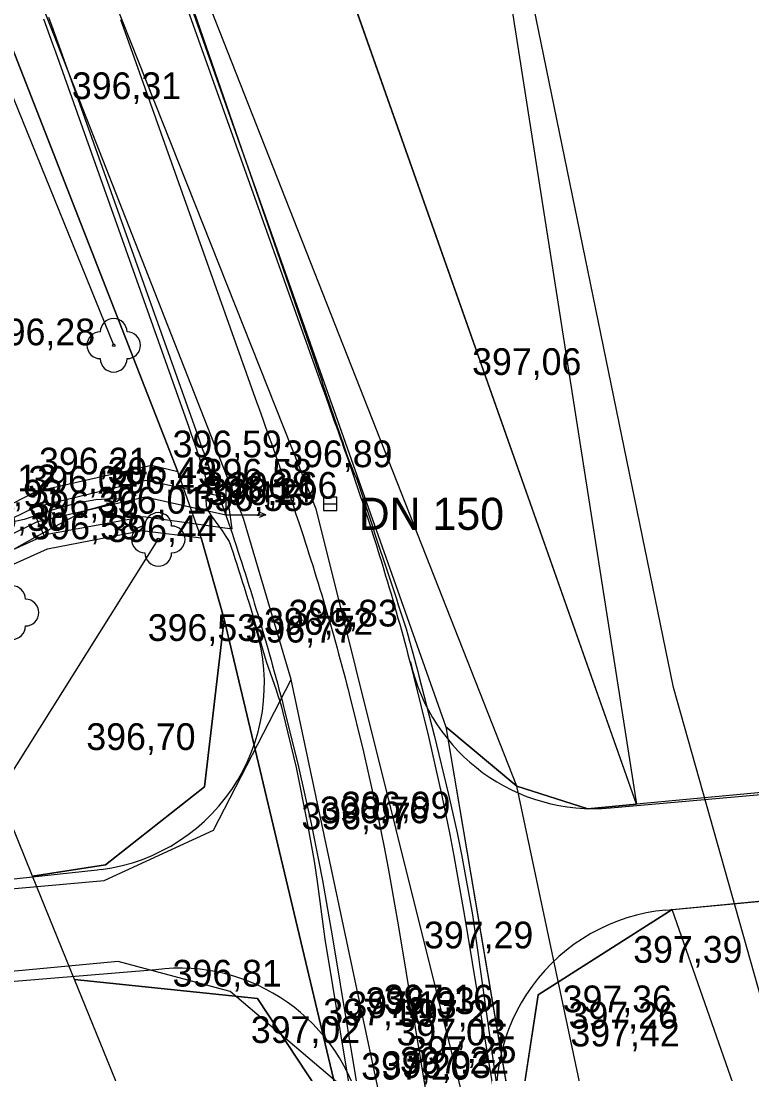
# Model space of a CAD drawing. Extents: x -574342 to -507939, y -1144044 to -1123894.
# Drawn here: x -508438.6 to -508411.24, y -1143262.87 to -1143223.48 of the extents above; entities that cross this region are included whole.
import ezdxf

# ---------------------------------------------------------------- set-up
doc = ezdxf.new("R2010")
doc.units = 0
for name, color, linetype in [('01_PARCELY_NAVRH_PC', 7, 'Continuous'), ('01_PARCELY_NAVRH_VHO', 7, 'Continuous'), ('01_PARCELY_NAVRH_ZPF', 7, 'Continuous'), ('01_PARCELY_NAVRH_ŽP', 7, 'Continuous'), ('1000', 7, 'Continuous'), ('15', 7, 'Continuous'), ('21', 7, 'Continuous'), ('37', 7, 'Continuous'), ('42', 7, 'Continuous'), ('52', 7, 'Continuous'), ('54', 7, 'Continuous'), ('55', 7, 'Continuous'), ('60', 7, 'Continuous'), ('61', 7, 'Continuous'), ('cesty', 7, 'Continuous'), ('Level 255', 7, 'Continuous'), ('VRST VEDL', 7, 'Continuous')]:
    doc.layers.add(name, color=color, linetype=linetype)

msp = doc.modelspace()

# ---------------------------------------------------------------- linework, layer by layer
at = {"layer": '01_PARCELY_NAVRH_PC'}
for points in [[(-508426.41, -1143265.09), (-508431, -1143245.85), (-508431.86, -1143242.81), (-508432.73, -1143240.34), (-508445.99, -1143206.42), (-508454.33, -1143183.49), (-508456.87, -1143173.84), (-508463.3, -1143163.03), (-508476.26, -1143134.7), (-508479.46, -1143126.74), (-508474.05, -1143124.14), (-508467.92, -1143139.18), (-508459.97, -1143152.33), (-508456.09, -1143158.71), (-508451.57, -1143168.14), (-508437.66, -1143207.58), (-508425.52, -1143241.92), (-508422.7, -1143249.88), (-508420.08, -1143265.35)], [(-508026.763, -1143130.616), (-508028.05, -1143130.95), (-508188.91, -1143212.74), (-508197.69, -1143215.86), (-508325.49, -1143244.3), (-508415.56, -1143252.78), (-508417.38, -1143252.95), (-508420.04, -1143252.1), (-508422.7, -1143249.88), (-508420.08, -1143265.35), (-508419.24, -1143259.91), (-508414.23, -1143256.72), (-508401.25, -1143255.47), (-508381.42, -1143253.61), (-508325.37, -1143248.48), (-508191.76, -1143218.68), (-508026.763, -1143135.132)]]:
    msp.add_lwpolyline(points, dxfattribs=at)
msp.add_lwpolyline([(-508431, -1143245.85), (-508426.41, -1143265.09), (-508429.75, -1143260.04), (-508436.6, -1143259.34), (-508438.17, -1143255.47), (-508435.43, -1143255.05), (-508431.73, -1143252.13)], close=True, dxfattribs=at)
at = {"layer": '01_PARCELY_NAVRH_VHO'}
msp.add_lwpolyline([(-508433.97, -1143265.8), (-508436.6, -1143259.34), (-508438.17, -1143255.47), (-508441.16, -1143248.09), (-508442.91, -1143245.61), (-508437.61, -1143243.22), (-508434.06, -1143242.54), (-508431.86, -1143242.81), (-508432.73, -1143240.34), (-508433.72, -1143240.11), (-508438.05, -1143241.09), (-508444.11, -1143244.2), (-508446.56, -1143243.12), (-508452.58, -1143244.39), (-508461.81, -1143244.49), (-508467.98, -1143243.62)], dxfattribs=at)
at = {"layer": '01_PARCELY_NAVRH_ZPF'}
msp.add_lwpolyline([(-508263.293, -1143480.706), (-508286.971, -1143456.793), (-508322.95, -1143422.01), (-508338.96, -1143386.69), (-508345.08, -1143368.8), (-508351.18, -1143342.58), (-508355.53, -1143335.68), (-508361.58, -1143328.14), (-508368.91, -1143322.84), (-508376.72, -1143318.72), (-508388.31, -1143315.9), (-508393.87, -1143311.09), (-508396.73, -1143306.67), (-508414.23, -1143256.72), (-508401.25, -1143255.47), (-508393.61, -1143260.11), (-508380.74, -1143302.76), (-508356.16, -1143314.16), (-508344.92, -1143326.36), (-508313.43, -1143410.52), (-508253.01, -1143468.5)], dxfattribs=at)
at = {"layer": '01_PARCELY_NAVRH_ŽP'}
for points in [[(-508540.355, -1142847.7), (-508503.94, -1143018.7), (-508499.26, -1143041.98), (-508491.15, -1143065.29), (-508474.05, -1143124.14), (-508467.92, -1143139.18), (-508459.97, -1143152.33), (-508456.09, -1143158.71), (-508451.57, -1143168.14), (-508437.66, -1143207.58), (-508425.52, -1143241.92), (-508422.7, -1143249.88), (-508420.04, -1143252.1), (-508417.38, -1143252.95), (-508415.56, -1143252.78), (-508448.24, -1143160.16), (-508453.75, -1143145.01), (-508465.11, -1143123.03), (-508471.48, -1143106.99), (-508484.55, -1143061.98), (-508495.62, -1143031.06), (-508523.23, -1142904.28), (-508534.61, -1142847.7)], [(-508338.96, -1143386.69), (-508345.08, -1143368.8), (-508351.18, -1143342.58), (-508355.53, -1143335.68), (-508361.58, -1143328.14), (-508368.91, -1143322.84), (-508376.72, -1143318.72), (-508388.31, -1143315.9), (-508393.87, -1143311.09), (-508396.73, -1143306.67), (-508414.23, -1143256.72), (-508419.24, -1143259.91), (-508420.08, -1143265.35), (-508416.18, -1143288.91), (-508414.34, -1143296.2), (-508410.3, -1143304.94), (-508406.96, -1143310.33), (-508402.64, -1143313.55), (-508394.5, -1143317.14), (-508377.05, -1143323.29), (-508363.05, -1143330.55), (-508352.96, -1143343.32), (-508344.87, -1143376.79)]]:
    msp.add_lwpolyline(points, dxfattribs=at)
for points in [[(-508415.56, -1143252.78), (-508448.24, -1143160.16), (-508453.75, -1143145.01), (-508465.11, -1143123.03), (-508471.48, -1143106.99), (-508484.55, -1143061.98), (-508446.15, -1143057.71)], [(-508455.43, -1143236.54), (-508453.14, -1143234.1), (-508452.04, -1143229.57), (-508450.69, -1143221.56), (-508452.8, -1143209.75), (-508452.72, -1143198.2), (-508454.33, -1143183.49), (-508445.99, -1143206.42), (-508432.73, -1143240.34), (-508433.72, -1143240.11), (-508438.05, -1143241.09), (-508444.11, -1143244.2), (-508446.56, -1143243.12), (-508452.58, -1143244.39)], [(-508442.91, -1143245.61), (-508437.61, -1143243.22), (-508434.06, -1143242.54), (-508431.86, -1143242.81), (-508431, -1143245.85), (-508431.73, -1143252.13), (-508435.43, -1143255.05), (-508438.17, -1143255.47), (-508441.16, -1143248.09)], [(-508436.6, -1143259.34), (-508429.75, -1143260.04), (-508426.41, -1143265.09), (-508422.28, -1143289.33), (-508418.17, -1143303.49), (-508414.82, -1143312.69), (-508407.39, -1143320.93), (-508402.47, -1143323.55), (-508412.73, -1143323), (-508414.59, -1143317.71), (-508420.1, -1143305.91), (-508426.78, -1143287.77), (-508433.97, -1143265.8)]]:
    msp.add_lwpolyline(points, close=True, dxfattribs=at)
at = {"layer": '1000'}
for points in [[(-508432.412, -1143222.893), (-508427.412, -1143236.927), (-508427.335, -1143237.143), (-508427.258, -1143237.36), (-508427.181, -1143237.576), (-508427.104, -1143237.793), (-508427.027, -1143238.009), (-508426.95, -1143238.226), (-508426.873, -1143238.442), (-508426.796, -1143238.659), (-508426.719, -1143238.875), (-508426.641, -1143239.091), (-508426.572, -1143239.287), (-508426.564, -1143239.308), (-508426.485, -1143239.53), (-508426.407, -1143239.752), (-508426.329, -1143239.975), (-508426.252, -1143240.197), (-508426.176, -1143240.42), (-508426.099, -1143240.643), (-508426.024, -1143240.866), (-508425.949, -1143241.089), (-508425.874, -1143241.312), (-508425.829, -1143241.447), (-508425.8, -1143241.536), (-508425.726, -1143241.76), (-508425.653, -1143241.983), (-508425.581, -1143242.207), (-508425.509, -1143242.432), (-508425.437, -1143242.656), (-508425.366, -1143242.881), (-508425.295, -1143243.105), (-508425.225, -1143243.33), (-508425.156, -1143243.555), (-508425.135, -1143243.624), (-508425.087, -1143243.78), (-508425.019, -1143244.006), (-508424.951, -1143244.231), (-508424.883, -1143244.457), (-508424.816, -1143244.683), (-508424.75, -1143244.909), (-508424.684, -1143245.135), (-508424.619, -1143245.361), (-508424.554, -1143245.587), (-508424.49, -1143245.814), (-508424.489, -1143245.816), (-508424.426, -1143246.041), (-508424.363, -1143246.267), (-508424.3, -1143246.494), (-508424.238, -1143246.722), (-508424.176, -1143246.949), (-508424.115, -1143247.176), (-508424.054, -1143247.404), (-508423.994, -1143247.631), (-508423.934, -1143247.859), (-508423.892, -1143248.022), (-508423.345, -1143250.24), (-508422.847, -1143252.47), (-508422.554, -1143253.907), (-508422.399, -1143254.711), (-508422.001, -1143256.961), (-508420.867, -1143263.821)], [(-508432.226, -1143222.827), (-508427.357, -1143236.907), (-508427.284, -1143237.125), (-508427.209, -1143237.343), (-508427.135, -1143237.56), (-508427.061, -1143237.777), (-508426.987, -1143237.995), (-508426.912, -1143238.212), (-508426.838, -1143238.43), (-508426.763, -1143238.647), (-508426.688, -1143238.864), (-508426.613, -1143239.081), (-508426.546, -1143239.277), (-508426.538, -1143239.299), (-508426.462, -1143239.522), (-508426.386, -1143239.745), (-508426.31, -1143239.968), (-508426.216, -1143240.185), (-508426.124, -1143240.402), (-508426.031, -1143240.619), (-508425.953, -1143240.842), (-508425.875, -1143241.064), (-508425.799, -1143241.287), (-508425.755, -1143241.423), (-508425.725, -1143241.511), (-508425.652, -1143241.735), (-508425.579, -1143241.959), (-508425.506, -1143242.183), (-508425.434, -1143242.408), (-508425.362, -1143242.632), (-508425.29, -1143242.857), (-508425.219, -1143243.081), (-508425.146, -1143243.306), (-508425.071, -1143243.529), (-508425.048, -1143243.598), (-508424.996, -1143243.752), (-508424.921, -1143243.976), (-508424.846, -1143244.2), (-508424.772, -1143244.424), (-508424.698, -1143244.648), (-508424.624, -1143244.872), (-508424.55, -1143245.096), (-508424.477, -1143245.32), (-508424.405, -1143245.545), (-508424.332, -1143245.769), (-508424.331, -1143245.772), (-508424.26, -1143245.994), (-508424.188, -1143246.219), (-508424.123, -1143246.446), (-508424.061, -1143246.673), (-508423.998, -1143246.901), (-508423.936, -1143247.128), (-508423.874, -1143247.356), (-508423.813, -1143247.584), (-508423.752, -1143247.812), (-508423.708, -1143247.974), (-508423.137, -1143250.192), (-508422.599, -1143252.418), (-508422.277, -1143253.853), (-508422.116, -1143254.658), (-508421.696, -1143256.911), (-508420.73, -1143263.798)], [(-508437.754, -1143223.398), (-508437.642, -1143223.707), (-508437.531, -1143224.017), (-508437.419, -1143224.327), (-508437.307, -1143224.637), (-508432.319, -1143238.675), (-508432.242, -1143238.892), (-508432.165, -1143239.108), (-508432.089, -1143239.325), (-508432.016, -1143239.543), (-508431.946, -1143239.762), (-508431.876, -1143239.981), (-508431.807, -1143240.2), (-508431.737, -1143240.419), (-508431.668, -1143240.638), (-508431.599, -1143240.857), (-508431.625, -1143241.087), (-508431.629, -1143241.111), (-508431.677, -1143241.365), (-508431.668, -1143241.598), (-508431.591, -1143241.807), (-508431.466, -1143241.999), (-508431.331, -1143242.189), (-508431.197, -1143242.379), (-508431.062, -1143242.569), (-508430.929, -1143242.759), (-508430.802, -1143242.953), (-508430.759, -1143243.081), (-508430.732, -1143243.165), (-508430.663, -1143243.378), (-508430.593, -1143243.59), (-508430.524, -1143243.803), (-508430.455, -1143244.015), (-508430.386, -1143244.228), (-508430.318, -1143244.441), (-508430.25, -1143244.654), (-508430.184, -1143244.867), (-508430.117, -1143245.081), (-508430.097, -1143245.147), (-508430.052, -1143245.295), (-508429.986, -1143245.508), (-508429.922, -1143245.723), (-508429.858, -1143245.937), (-508429.794, -1143246.151), (-508429.732, -1143246.366), (-508429.669, -1143246.58), (-508429.608, -1143246.795), (-508429.547, -1143247.01), (-508429.486, -1143247.226), (-508429.485, -1143247.228), (-508429.42, -1143247.439), (-508429.345, -1143247.651), (-508429.272, -1143247.862), (-508429.199, -1143248.074), (-508429.126, -1143248.286), (-508429.054, -1143248.499), (-508428.983, -1143248.711), (-508428.912, -1143248.924), (-508428.847, -1143249.138), (-508428.808, -1143249.293), (-508428.301, -1143251.405), (-508427.873, -1143253.534), (-508427.631, -1143254.906), (-508427.514, -1143255.675), (-508427.224, -1143257.825), (-508426.094, -1143264.685)], [(-508437.564, -1143223.33), (-508437.454, -1143223.64), (-508437.343, -1143223.951), (-508437.233, -1143224.261), (-508437.122, -1143224.571), (-508432.123, -1143238.605), (-508432.045, -1143238.821), (-508431.968, -1143239.038), (-508431.891, -1143239.254), (-508431.814, -1143239.471), (-508431.737, -1143239.687), (-508431.66, -1143239.904), (-508431.583, -1143240.12), (-508431.506, -1143240.336), (-508431.429, -1143240.553), (-508431.351, -1143240.769), (-508431.282, -1143240.965), (-508431.275, -1143240.985), (-508431.2, -1143241.196), (-508431.125, -1143241.408), (-508431.051, -1143241.619), (-508430.978, -1143241.831), (-508430.905, -1143242.043), (-508430.833, -1143242.255), (-508430.761, -1143242.467), (-508430.689, -1143242.679), (-508430.618, -1143242.891), (-508430.575, -1143243.02), (-508430.548, -1143243.104), (-508430.478, -1143243.317), (-508430.408, -1143243.53), (-508430.339, -1143243.743), (-508430.27, -1143243.956), (-508430.202, -1143244.17), (-508430.135, -1143244.383), (-508430.068, -1143244.597), (-508430.001, -1143244.811), (-508429.935, -1143245.025), (-508429.915, -1143245.091), (-508429.869, -1143245.239), (-508429.804, -1143245.453), (-508429.74, -1143245.668), (-508429.676, -1143245.883), (-508429.612, -1143246.097), (-508429.549, -1143246.312), (-508429.486, -1143246.527), (-508429.424, -1143246.743), (-508429.362, -1143246.958), (-508429.301, -1143247.173), (-508429.301, -1143247.176), (-508429.241, -1143247.389), (-508429.18, -1143247.605), (-508429.121, -1143247.821), (-508429.062, -1143248.037), (-508429.003, -1143248.253), (-508428.945, -1143248.469), (-508428.887, -1143248.686), (-508428.83, -1143248.902), (-508428.773, -1143249.119), (-508428.733, -1143249.274), (-508428.212, -1143251.384), (-508427.739, -1143253.505), (-508427.46, -1143254.872), (-508427.313, -1143255.637), (-508426.934, -1143257.777), (-508425.8, -1143264.636)]]:
    msp.add_lwpolyline(points, dxfattribs=at)
at = {"layer": '21'}
msp.add_lwpolyline([(-508434.878, -1143223.422), (-508434.767, -1143223.732), (-508429.767, -1143237.766), (-508429.69, -1143237.982), (-508429.613, -1143238.199), (-508429.536, -1143238.415), (-508429.459, -1143238.632), (-508429.382, -1143238.848), (-508429.305, -1143239.065), (-508429.228, -1143239.281), (-508429.151, -1143239.497), (-508429.074, -1143239.714), (-508428.996, -1143239.93), (-508428.927, -1143240.126), (-508428.919, -1143240.147), (-508428.843, -1143240.363), (-508428.766, -1143240.58), (-508428.69, -1143240.797), (-508428.615, -1143241.014), (-508428.54, -1143241.231), (-508428.466, -1143241.449), (-508428.392, -1143241.666), (-508428.319, -1143241.884), (-508428.246, -1143242.102), (-508428.202, -1143242.234), (-508428.174, -1143242.32), (-508428.102, -1143242.538), (-508428.031, -1143242.757), (-508427.96, -1143242.975), (-508427.889, -1143243.194), (-508427.82, -1143243.413), (-508427.75, -1143243.632), (-508427.682, -1143243.851), (-508427.613, -1143244.07), (-508427.546, -1143244.29), (-508427.525, -1143244.358), (-508427.478, -1143244.51), (-508427.411, -1143244.73), (-508427.345, -1143244.949), (-508427.279, -1143245.17), (-508427.214, -1143245.39), (-508427.149, -1143245.61), (-508427.085, -1143245.831), (-508427.021, -1143246.052), (-508426.958, -1143246.273), (-508426.895, -1143246.494), (-508426.895, -1143246.496), (-508426.833, -1143246.715), (-508426.771, -1143246.936), (-508426.71, -1143247.158), (-508426.65, -1143247.379), (-508426.589, -1143247.601), (-508426.53, -1143247.823), (-508426.471, -1143248.045), (-508426.412, -1143248.267), (-508426.354, -1143248.489), (-508426.313, -1143248.648), (-508425.779, -1143250.812), (-508425.293, -1143252.988), (-508425.007, -1143254.39), (-508424.856, -1143255.174), (-508424.468, -1143257.369), (-508423.333, -1143264.228)], dxfattribs=at)
at = {"layer": '37'}
for points in [[(-508473.82, -1143129.8), (-508468.34, -1143141.31), (-508458.53, -1143158.76), (-508453.13, -1143170.86), (-508439.96, -1143210.5), (-508427.56, -1143241.73), (-508421.57, -1143265.72), (-508416.35, -1143292.6), (-508412.42, -1143304.7), (-508408.82, -1143311.83)], [(-508473.82, -1143129.8), (-508468.34, -1143141.31), (-508458.53, -1143158.76), (-508453.13, -1143170.86), (-508439.96, -1143210.5), (-508427.56, -1143241.73), (-508421.57, -1143265.72), (-508416.35, -1143292.6), (-508412.42, -1143304.7), (-508408.82, -1143311.83)], [(-508408.82, -1143311.83), (-508404.37, -1143317.04), (-508398.21, -1143321.18), (-508393.66, -1143322.44), (-508393.79, -1143324.58), (-508400.56, -1143323.11), (-508406.32, -1143319.06), (-508411.41, -1143313.16), (-508415.31, -1143305.9), (-508419.33, -1143292.88), (-508424.96, -1143264.72), (-508428.49, -1143248.11), (-508430.27, -1143242.09), (-508442.28, -1143211.48), (-508455.59, -1143171.17), (-508460.82, -1143160.05), (-508470.5, -1143142.85)], [(-508408.82, -1143311.83), (-508404.37, -1143317.04), (-508398.21, -1143321.18), (-508393.66, -1143322.44), (-508393.79, -1143324.58), (-508400.56, -1143323.11), (-508406.32, -1143319.06), (-508411.41, -1143313.16), (-508415.31, -1143305.9), (-508419.33, -1143292.88), (-508424.96, -1143264.72), (-508428.49, -1143248.11), (-508430.27, -1143242.09), (-508442.28, -1143211.48), (-508455.59, -1143171.17), (-508460.82, -1143160.05), (-508470.5, -1143142.85)]]:
    msp.add_lwpolyline(points, dxfattribs=at)
at = {"layer": '42'}
msp.add_lwpolyline([(-508320.88, -1143423.96), (-508327.62, -1143411.06), (-508338.78, -1143387.2), (-508344.67, -1143370.01), (-508350.79, -1143346.58), (-508354.96, -1143336.71), (-508361.36, -1143329.02), (-508368.91, -1143322.84), (-508376.72, -1143318.72), (-508388.31, -1143315.9), (-508393.87, -1143311.09), (-508396.73, -1143306.67), (-508407.7, -1143271.35), (-508414.18, -1143248.41), (-508420.68, -1143216.75), (-508423.64, -1143189.02), (-508427.95, -1143159.6), (-508434.68, -1143117.69), (-508439.72, -1143092.94), (-508444.13, -1143060.48), (-508445.89, -1143059.01)], dxfattribs=at)
msp.add_lwpolyline([(-508320.88, -1143423.96), (-508327.62, -1143411.06), (-508338.78, -1143387.2), (-508344.67, -1143370.01), (-508350.79, -1143346.58), (-508354.96, -1143336.71), (-508361.36, -1143329.02), (-508368.91, -1143322.84), (-508376.72, -1143318.72), (-508388.31, -1143315.9), (-508393.87, -1143311.09), (-508396.73, -1143306.67), (-508407.7, -1143271.35), (-508414.18, -1143248.41), (-508420.68, -1143216.75), (-508423.64, -1143189.02), (-508427.95, -1143159.6), (-508434.68, -1143117.69), (-508439.72, -1143092.94), (-508444.13, -1143060.48), (-508445.89, -1143059.01)], dxfattribs=at)
at = {"layer": '52'}
for p, q in [((-508430.93, -1143240.95), (-508430.93, -1143241.95)), ((-508427.28, -1143241.54), (-508426.78, -1143241.54)), ((-508430.93, -1143241.95), (-508429.43, -1143241.95)), ((-508429.43, -1143241.95), (-508429.68, -1143241.85)), ((-508429.43, -1143241.95), (-508429.68, -1143242.05))]:
    msp.add_line(p, q, dxfattribs=at)
msp.add_lwpolyline([(-508427.28, -1143241.79), (-508426.78, -1143241.79), (-508426.78, -1143241.29), (-508427.28, -1143241.29)], close=True, dxfattribs=at)
at = {"layer": '54'}
for centre in [(-508435.13, -1143235.61), (-508433.46, -1143242.87)]:
    msp.add_circle(centre, 0.05, dxfattribs=at)
for centre, start, end in [((-508435.13, -1143235.11), 0, 180), ((-508435.63, -1143235.61), 90, 270), ((-508434.63, -1143235.61), 270, 90), ((-508435.13, -1143236.11), 180, 0), ((-508433.46, -1143242.37), 0, 180), ((-508433.96, -1143242.87), 90, 270), ((-508432.96, -1143242.87), 270, 90), ((-508433.46, -1143243.37), 180, 0), ((-508438.93, -1143245.11), 0, 180), ((-508438.43, -1143245.61), 270, 90), ((-508438.93, -1143246.11), 180, 0)]:
    msp.add_arc(centre, 0.5, start, end, dxfattribs=at)
at = {"layer": '55'}
for points in [[(-508435.13, -1143235.61), (-508444.83, -1143211.72), (-508456.61, -1143175.27)], [(-508435.13, -1143235.61), (-508444.83, -1143211.72), (-508456.61, -1143175.27)], [(-508410.24, -1143298.34), (-508420.04, -1143252.1), (-508438.58, -1143205.02)], [(-508410.24, -1143298.34), (-508420.04, -1143252.1), (-508438.58, -1143205.02)], [(-508471.18, -1143256.14), (-508439.22, -1143252.04), (-508433.46, -1143242.87)], [(-508471.18, -1143256.14), (-508439.22, -1143252.04), (-508433.46, -1143242.87)], [(-508495.48, -1143259.17), (-508472.43, -1143258.93), (-508435.48, -1143255.63), (-508431.4, -1143253.75), (-508428.49, -1143248.11)], [(-508495.48, -1143259.17), (-508472.43, -1143258.93), (-508435.48, -1143255.63), (-508431.4, -1143253.75), (-508428.49, -1143248.11)], [(-508424.96, -1143264.72), (-508430.77, -1143259.78), (-508434.96, -1143258.66), (-508472.39, -1143262.17), (-508495.8, -1143262.63)], [(-508424.96, -1143264.72), (-508430.77, -1143259.78), (-508434.96, -1143258.66), (-508472.39, -1143262.17), (-508495.8, -1143262.63)]]:
    msp.add_lwpolyline(points, dxfattribs=at)
at = {"layer": '60'}
for points in [[(-508480.22, -1143257.91), (-508469.09, -1143257.11), (-508446.3, -1143255.05), (-508439.65, -1143253.6), (-508441.71, -1143248.16), (-508443.77, -1143245.44), (-508437.62, -1143242.68), (-508434.01, -1143242.01), (-508430.69, -1143242.47), (-508430.86, -1143241.32), (-508433.93, -1143240.67), (-508438.09, -1143241.68), (-508444.43, -1143244.81), (-508446.95, -1143243.83), (-508452.85, -1143244.81)], [(-508480.22, -1143257.91), (-508469.09, -1143257.11), (-508446.3, -1143255.05), (-508439.65, -1143253.6), (-508441.71, -1143248.16), (-508443.77, -1143245.44), (-508437.62, -1143242.68), (-508434.01, -1143242.01), (-508430.69, -1143242.47), (-508430.86, -1143241.32), (-508433.93, -1143240.67), (-508438.09, -1143241.68), (-508444.43, -1143244.81), (-508446.95, -1143243.83), (-508452.85, -1143244.81)], [(-508445.36, -1143246.6), (-508444.15, -1143245.24), (-508437.98, -1143242.2), (-508433.95, -1143241.28), (-508430.93, -1143241.95)], [(-508445.36, -1143246.6), (-508444.15, -1143245.24), (-508437.98, -1143242.2), (-508433.95, -1143241.28), (-508430.93, -1143241.95)]]:
    msp.add_lwpolyline(points, dxfattribs=at)
at = {"layer": '61'}
for p in [(-508438.198, -1143241.739), (-508438.198, -1143241.739), (-508437.731, -1143242.73), (-508437.731, -1143242.73)]:
    msp.add_line(p, (-508437.97, -1143242.2), dxfattribs=at)
at = {"layer": 'cesty'}
for p, q in [((-508416.534, -1143252.912), (-508328.343, -1143245.177)), ((-508414.463, -1143256.736), (-508400.637, -1143255.444))]:
    msp.add_line(p, q, dxfattribs=at)
for points in [[(-508435.592, -1143255.219), (-508435.753, -1143255.24), (-508470.415, -1143258.999)], [(-508433.558, -1143258.97), (-508433.558, -1143258.97), (-508470.134, -1143261.986)]]:
    msp.add_lwpolyline(points, dxfattribs=at)
for centre, start, end in [((-508436.49, -1143248.277), 277.3688, 20.5544), ((-508417.185, -1143245.942), 192.4584, 275.3361), ((-508413.812, -1143263.705), 95.3361, 192.4584), ((-508432.66, -1143265.912), 12.4584, 97.3688)]:
    msp.add_arc(centre, 7, start, end, dxfattribs=at)
at = {"layer": 'VRST VEDL'}
msp.add_lwpolyline([(-508439.823, -1143243.772), (-508438.068, -1143242.792), (-508436.85, -1143242.127), (-508436.168, -1143241.778), (-508436.022, -1143241.743), (-508435.778, -1143241.676), (-508435.437, -1143241.577), (-508434.997, -1143241.446), (-508434.912, -1143241.372), (-508435.179, -1143241.354), (-508435.8, -1143241.392), (-508436.557, -1143241.533), (-508437.45, -1143241.776), (-508438.479, -1143242.123), (-508439.11, -1143242.264)], dxfattribs=at)

# ---------------------------------------------------------------- texts
at = {"layer": '15'}
msp.add_text('DN 150', height=1.2, dxfattribs=at).set_placement((-508425.961, -1143242.514))
msp.add_text('DN 150', height=1.2, dxfattribs=at).set_placement((-508425.961, -1143242.514))
at = {"layer": 'Level 255'}
for s, p in [('396,31', (-508436.695, -1143226.4)), ('396,28', (-508439.915, -1143235.61)), ('397,06', (-508421.715, -1143236.72)), ('396,59', (-508432.925, -1143239.8)), ('396,89', (-508428.785, -1143240.17)), ('396,21', (-508437.925, -1143240.44)), ('396,12', (-508441.345, -1143241.07)), ('396,49', (-508435.355, -1143240.8)), ('396,58', (-508431.795, -1143240.86)), ('396,04', (-508438.325, -1143241.13)), ('396,42', (-508435.445, -1143241.16)), ('396,14', (-508431.785, -1143241.49)), ('396,66', (-508430.845, -1143241.35)), ('395,93', (-508441.125, -1143241.64)), ('396,55', (-508432.125, -1143241.81)), ('396,29', (-508431.605, -1143241.59)), ('396,36', (-508438.275, -1143242.06)), ('396,01', (-508435.755, -1143241.91)), ('396,30', (-508440.985, -1143242.55)), ('396,58', (-508438.245, -1143242.87)), ('396,44', (-508435.365, -1143242.97)), ('396,83', (-508428.585, -1143246.13)), ('396,52', (-508429.505, -1143246.44)), ('396,53', (-508433.855, -1143246.67)), ('396,77', (-508430.195, -1143246.73)), ('396,70', (-508436.155, -1143250.75)), ('396,99', (-508426.615, -1143253.31)), ('396,76', (-508427.415, -1143253.49)), ('396,97', (-508428.105, -1143253.72)), ('397,29', (-508423.515, -1143258.17)), ('397,39', (-508415.685, -1143258.71)), ('396,81', (-508432.925, -1143259.6)), ('397,13', (-508426.385, -1143260.78)), ('396,93', (-508425.705, -1143260.63)), ('397,16', (-508425.025, -1143260.53)), ('397,36', (-508418.325, -1143260.56)), ('397,10', (-508427.285, -1143261.05)), ('397,21', (-508424.485, -1143261.1)), ('397,26', (-508418.105, -1143261.17)), ('397,02', (-508429.995, -1143261.71)), ('397,03', (-508424.545, -1143261.8)), ('397,42', (-508418.035, -1143261.84)), ('397,25', (-508424.145, -1143262.46)), ('397,20', (-508425.865, -1143263.08)), ('396,93', (-508425.095, -1143263.02)), ('397,22', (-508424.415, -1143262.86))]:
    msp.add_text(s, height=1, dxfattribs=at).set_placement(p)

doc.saveas('drawing.dxf')
